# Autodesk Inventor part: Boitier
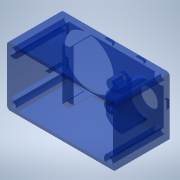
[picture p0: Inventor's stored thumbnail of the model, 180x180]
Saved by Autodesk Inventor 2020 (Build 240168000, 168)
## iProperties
Created: 2002-01
Part Number: Boitier
Project: Servo
Material: Polycarbonate, fumée
Document SubType Name: Modélisation
Designer: Philippe
Density: 1.2 g/cm^3
Appearance: Bleu (transparent)
Mass: 0.694521 g
Surface Area: 18.7298 cm^2
Volume: 0.578768 cm^3
Control State: 0
Master: False
Checked Out: False
Shininess: 20.0
Angle Display Precision: 2
Document Length Units: 11269
Document Angle Units: 11279
Document Time Units: 11290
Document Mass Units: 11283
Document Length Units Precision: 3
Document Angle Units Precision: 2
Density: 0.0
Volumn: 0.0
Area: 0.0
PropertySet Name: Model Information
Author: Philippe
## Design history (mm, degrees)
sketch "Esquisse1"
  geometry: L1 (0, 0)-(21, 0); L2 (21, 0)-(21, 10.3); L3 (21, 10.3)-(0, 10.3); L4 (0, 10.3)-(0, 0)
  constraints: 8 end point, 2 parallel, 1 horizontal, 1 perpendicular, 1 other
  dimensions: "d0" = 21 distance of L1.start L1.end; "d1" = 10.3 distance of L3.end L1.start
extrude "Extrusion1" new body sketch "Esquisse1" stored distance "d2" = 11.4; taper "d3" = 0 deg
fillet "Congé1" dims "d4" = 0.6
feature "Coque1" dims "d5" = 0.6
sketch "Esquisse3"
  geometry: L1 (0, -11.4)-(19.8, -11.4) reference; L2 (20.4, -0.6)-(20.4, -10.8) reference; 1 further point
  dimensions: "d8" = 3.6 distance from line of L2 point (16.8, -5.7); "d9" = 5.7 distance from line of L1 point (16.8, -5.7) (= 0.5 x d2)
hole "Perçage1" sketch "Esquisse3" at (16.8, -5.7) diameter "d10" = 3.8; stored, may be unused: countersink angle "d14" = 82 deg, drill point angle "d16" = 118 deg; dims "d11" = 6, "d12" = 4, "d13" = 2, "d15" = 8
sketch "Esquisse4"
  geometry: L1 (0, 0)-(19.8, 0) reference; L2 (0, -10.2)-(0, 0) reference; L3 (19.8, -10.2)-(0, -10.2) reference; L4 (4.5, -10.2)-(5.9, -10.2); L5 (5.9, -10.2)-(5.9, 0); L6 (5.9, 0)-(4.5, 0); L7 (4.5, 0)-(4.5, -10.2); L8 (19.8, -10.2)-(19.8, 0) reference; L9 (4.5, -2.7)-(0, -2.7); L10 (4.5, -7.5)-(0, -7.5); L11 (19.8, 0.6)-(0, 0.6) reference
  constraints: 12 end point, 6 point on line, 3 perpendicular, 2 parallel, 1 horizontal
  dimensions: "d17" = 1.4 distance between parallel lines of L5 L7; "d18" = 4.5 distance between parallel lines of L7 L2; "d44" = 4.8 distance between parallel lines of L10 L9; "d45" = 3.3 distance between parallel lines of L11 L9 (= -0.5 x d44 + 0.5 x d2)
extrude "Extrusion3" join sketch "Esquisse4" distance "d19" = 4.2; taper "d20" = 0 deg
extrude "Extrusion6" join sketch "Esquisse4" distance "d46" = 3; taper "d47" = 0 deg
sketch "Esquisse6"
  geometry: L1 (20.4, -0.6)-(20.4, -10.8) reference; L2 (16.8, -5.7)-(5.2, -5.7); C1 r 1.9 at (16.8, -5.7) reference
  constraints: 2 end point, 1 perpendicular
  dimensions: "d22" = 11.6 distance of L2.start L2.end
hole "Perçage2" sketch "Esquisse6" at (5.2, -5.7) diameter "d23" = 10; stored, may be unused: countersink angle "d27" = 82 deg, drill point angle "d29" = 0 deg; dims "d24" = 6, "d25" = 4, "d26" = 2, "d28" = 4
sketch "Esquisse7"
  geometry: C1 r 1.9 at (16.8, -5.7) reference; C2 r 1 at (11.2, -5.7); C3 r 0.5 at (11.2, -5.7)
  constraints: 2 centre point, 1 coincident
  dimensions: "d30" = 5.6 distance of C1.centre C3.centre; "d31" = 1 diameter of C3; "d32" = 2 diameter of C2
extrude "Extrusion4" join sketch "Esquisse7" distance "d33" = 0.6; taper "d34" = 0 deg
sketch "Esquisse8"
  geometry: L1 (19.8, 0)-(0, 0) reference; L2 (20.4, -0.6)-(20.4, -10.8) reference; L3 (19.8, -0.6)-(0, -0.6) reference; L4 (7.8, -0.6)-(9.3, -0.6); L5 (9.3, -0.6)-(9.3, -1.1); L6 (9.3, -1.1)-(7.8, -1.1); L7 (7.8, -1.1)-(7.8, -0.6); L8 (13.8, -0.6)-(15.3, -0.6); L9 (15.3, -0.6)-(15.3, -1.1); L10 (15.3, -1.1)-(13.8, -1.1); L11 (13.8, -1.1)-(13.8, -0.6); L12 (19.8, -10.8)-(19.8, -0.6) reference; L13 (19.8, -4.95)-(19.3, -4.95); L14 (19.3, -4.95)-(19.3, -6.45); L15 (19.3, -6.45)-(19.8, -6.45); L16 (19.8, -6.45)-(19.8, -4.95); L17 (15.3, -10.8)-(13.8, -10.8); L18 (13.8, -10.8)-(13.8, -10.3); L19 (13.8, -10.3)-(15.3, -10.3); L20 (15.3, -10.3)-(15.3, -10.8); L21 (9.3, -10.8)-(7.8, -10.8); L22 (7.8, -10.8)-(7.8, -10.3); L23 (7.8, -10.3)-(9.3, -10.3); L24 (9.3, -10.3)-(9.3, -10.8); L25 (0, -0.6)-(0, -10.8) reference; L26 (0, -2.2)-(0.5, -2.2); L27 (0.5, -2.2)-(0.5, -3.7); L28 (0.5, -3.7)-(0, -3.7); L29 (0, -3.7)-(0, -2.2); L30 (0, -7.7)-(0.5, -7.7); L31 (0.5, -7.7)-(0.5, -9.2); L32 (0.5, -9.2)-(0, -9.2); L33 (0, -9.2)-(0, -7.7); L34 (5.9, -10.8)-(19.8, -10.8) reference; 1 further point
  constraints: 56 end point, 14 parallel, 12 equal length, 7 horizontal, 7 perpendicular, 5 point on line, 4 collinear
  dimensions: "d35" = 0.5 distance of L26.start L26.end; "d36" = 1.5 distance of L26.end L27.end; "d37" = 7.5 distance between parallel lines of L9 L7; "d38" = 7 distance between parallel lines of L32 L26; "d39" = 4.95 distance between parallel lines of L13 L1; "d40" = 2.2 distance between parallel lines of L26 L1; "d41" = 6.6 distance between parallel lines of L2 L18
extrude "Extrusion5" join sketch "Esquisse8" distance "d42" = 0.5; taper "d43" = 0 deg
sketch "Esquisse9"
  geometry: L1 (-0.6, -0.6)-(-0.6, -10.8) reference; L2 (0, -11.4)-(19.8, -11.4) reference; L3 (13.8, -10.8)-(13.8, -10.3) reference; L4 (13.8, -10.3)-(15.3, -10.3) reference; L5 (15.3, -10.3)-(15.3, -10.8) reference; L6 (15.3, -10.8)-(13.8, -10.8) reference; L7 (13.8, -0.6)-(15.3, -0.6) reference; L8 (15.3, -0.6)-(15.3, -1.1) reference; L9 (15.3, -1.1)-(13.8, -1.1) reference; L10 (13.8, -1.1)-(13.8, -0.6) reference; L11 (0, -2.2)-(0.5, -2.2) reference; L12 (0.5, -2.2)-(0.5, -3.7) reference; L13 (0.5, -3.7)-(0, -3.7) reference; L14 (0, -3.7)-(0, -2.2) reference; L15 (7.8, -0.6)-(9.3, -0.6) reference; L16 (9.3, -0.6)-(9.3, -1.1) reference; L17 (9.3, -1.1)-(7.8, -1.1) reference; L18 (7.8, -1.1)-(7.8, -0.6) reference; L19 (0, -7.7)-(0.5, -7.7) reference; L20 (0.5, -7.7)-(0.5, -9.2) reference; L21 (0.5, -9.2)-(0, -9.2) reference; L22 (0, -9.2)-(0, -7.7) reference; L23 (19.8, -4.95)-(19.8, -6.45) reference; L24 (19.8, -6.45)-(19.3, -6.45) reference; L25 (19.3, -6.45)-(19.3, -4.95) reference; L26 (19.3, -4.95)-(19.8, -4.95) reference; L27 (7.8, -10.8)-(7.8, -10.3) reference; L28 (7.8, -10.3)-(9.3, -10.3) reference; L29 (9.3, -10.3)-(9.3, -10.8) reference; L30 (9.3, -10.8)-(7.8, -10.8) reference; L31 (19.8, 0)-(0, 0) reference; L32 (20.4, -0.6)-(20.4, -10.8) reference; C1 r 1.15 at (0.6, -10.2); C2 r 1.15 at (0.6, -1.2); C3 r 1.15 at (19.2, -1.2); C4 r 1.15 at (19.2, -10.2); C5 r 0.5 at (0.6, -10.2); C6 r 0.5 at (0.6, -1.2); C7 r 0.5 at (19.2, -1.2); C8 r 0.5 at (19.2, -10.2); C9 r 1.9 at (16.8, -5.7) reference; C10 r 5 at (5.2, -5.7) reference; C11 r 1 at (11.2, -5.7) reference; A1 r 0.6 centre (19.8, -0.6) between (20.4, -0.6) and (19.8, 0) reference; A2 r 0.6 centre (0, -0.6) between (0, 0) and (-0.6, -0.6) reference; A3 r 0.6 centre (0, -10.8) between (-0.6, -10.8) and (0, -11.4) reference; A4 r 0.6 centre (19.8, -10.8) between (19.8, -11.4) and (20.4, -10.8) reference; 1 further point
  constraints: 8 centre point, 6 equal radius, 4 coincident, 2 horizontal alignment, 2 vertical alignment
  dimensions: "d48" = 9 distance of C1.centre C2.centre; "d49" = 1.2 distance from line of C1.centre L2 (= -0.5 x d48 + 0.5 x d2); "d50" = 18.6 distance of C4.centre C1.centre; "d51" = 1.2 distance from line of C2.centre L1; "d52" = 2.3 diameter of C1; "d53" = 1 diameter of C6
extrude "Extrusion7" join sketch "Esquisse9" distance "d54" = 10.3 (= d1); taper "d55" = 0 deg
extrude "Extrusion8" cut sketch "Esquisse9" extent not by distance; stored distance "d56" = 10.3 (= d1); taper "d57" = 0 deg
sketch "Esquisse11"
  geometry: L1 (13.019, -5.1)-(0.7, -5.1) reference; L2 (11.6, 3)-(11.6, 3.6); L3 (8.5, 1.83)-(8.5, -1.83); L4 (11.6, -3)-(11.6, -3.6); L5 (9.1, 1.658)-(9.1, -1.658); C1 r 1.9 at (11.6, 0) reference; A1 r 3.6 centre (11.6, 0) between (11.6, 3.6) and (8.5, 1.83); A2 r 3.6 centre (11.6, 0) between (8.5, -1.83) and (11.6, -3.6); A3 r 3 centre (11.6, 0) between (11.6, 3) and (9.1, 1.658); A4 r 3 centre (11.6, 0) between (9.1, -1.658) and (11.6, -3)
  constraints: 8 end point, 8 point on circle, 4 centre point, 2 parallel, 1 coincident, 1 collinear, 1 perpendicular
  dimensions: "d58" = 0.6 distance of L2.start L2.end; "d59" = 0.6 distance of L4.start L4.end; "d61" = 0.6 distance between parallel lines of L3 L5; "d62" = 3 radius of A3; "d63" = 3 radius of A4; "d64" = 2.5 distance from line of L5 C1.centre; "d65" = 3.6 radius of A2; "d66" = 3.6 radius of A1
extrude "Extrusion9" join sketch "Esquisse11" distance "d67" = 5; taper "d68" = 0 deg
extrude "Extrusion10" join sketch "Esquisse7" distance "d69" = 2; taper "d70" = 0 deg
extrude "Extrusion11" cut sketch "Esquisse7" distance "d71" = 1.4; taper "d72" = 0 deg
node "Solide1"
node "Corps solides"
node "Corps surfaciques"
